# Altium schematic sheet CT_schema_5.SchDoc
size 391 x 301 mm
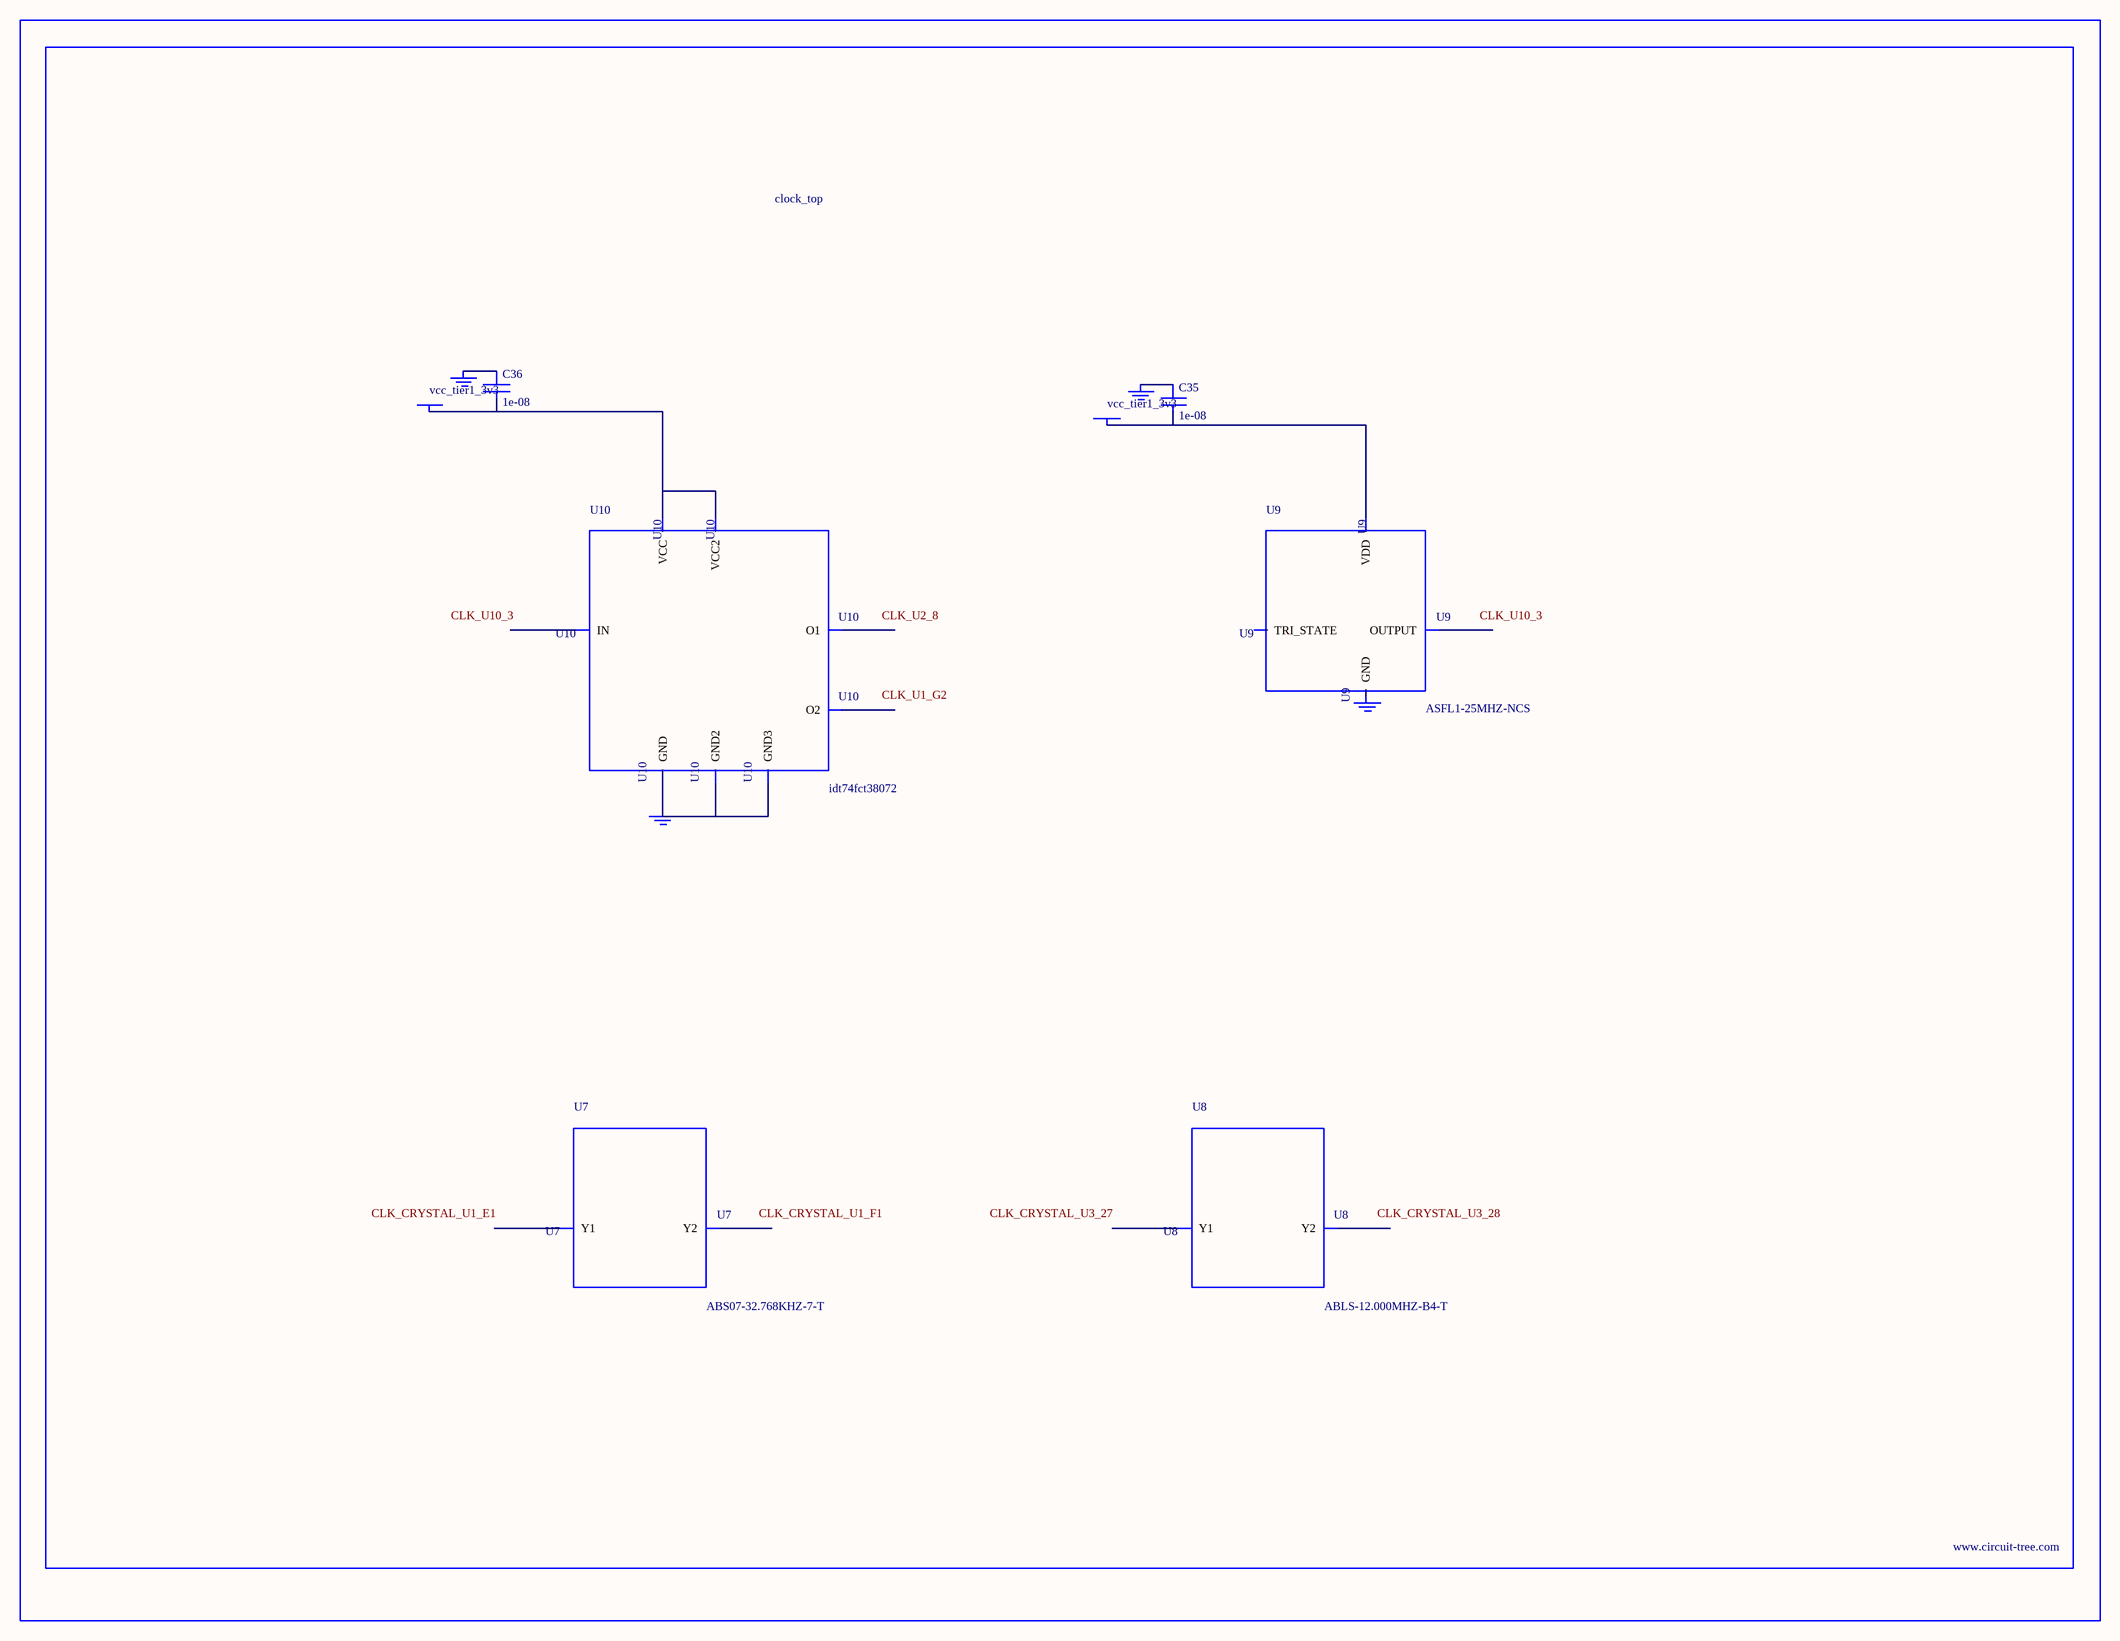
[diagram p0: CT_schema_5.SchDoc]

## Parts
BORDER4  (no value)
C35  1e-08  [C0402]
C36  1e-08  [C0402]
GND_INSTANCE_4_0  (no value)
GND_INSTANCE_4_1  (no value)
GND_INSTANCE_4_2  (no value)
GND_INSTANCE_4_3  (no value)
POWER_INSTANCE_4_0  vcc_tier1_3v3
POWER_INSTANCE_4_1  vcc_tier1_3v3
U7  ABS07-32.768KHZ-7-T  [ABS07-32.768KHZ-7-T]
U8  ABLS-12.000MHZ-B4-T  [ABLS-12.000MHZ-B4-T]
U9  ASFL1-25MHZ-NCS  [ASFL1]
U10  idt74fct38072  [IDT74FCT38072]

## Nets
NetC35_1: C35.1 GND_INSTANCE_4_0.0(GND)
NetC35_2: C35.2 POWER_INSTANCE_4_0.0(PWR) U9.4(VDD)
NetC36_1: C36.1 GND_INSTANCE_4_2.0(GND)
NetC36_2: C36.2 POWER_INSTANCE_4_1.0(PWR) U10.1(VCC) U10.2(VCC2)
NetGND_INSTANCE_4_3_0: GND_INSTANCE_4_3.0(GND) U10.4(GND) U10.5(GND2) U10.8(GND3)

Not connected (* = marked no-connect by the designer): GND_INSTANCE_4_1 0(GND); U7 1(Y1) 2(Y2); U8 1(Y1) 2(Y2); U9 1(TRI_STATE) 2(GND) 3(OUTPUT); U10 3(IN) 6(O2) 7(O1)

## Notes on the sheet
- Labels drawn without touching a wire or pin: CLK_CRYSTAL_U1_E1, CLK_CRYSTAL_U1_F1, CLK_CRYSTAL_U3_27, CLK_CRYSTAL_U3_28, CLK_U1_G2, CLK_U2_8, CLK_U10_3

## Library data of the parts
BORDER4 = BORDER_PAGE4
C35 C36 = C0402C103K3RAC
GND_INSTANCE_4_0-GND_INSTANCE_4_3 = GND
POWER_INSTANCE_4_0 POWER_INSTANCE_4_1 = PWR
